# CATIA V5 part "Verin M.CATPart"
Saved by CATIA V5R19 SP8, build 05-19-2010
Part number: Verin M
Bounding box of the stored display mesh (mm): x 178.09 to 425, y 45.135 to 94.865, z -159.495 to 24.818
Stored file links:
  C:\Users\ThinkMotion\Desktop\EU_thinkMotion\iao\IAO_MMS_Groupe3\rdalborgo\rdalborgo\Verin M.CATPart
  C:\Users\ThinkMotion\Desktop\EU_thinkMotion\iao\IAO_MMS_Groupe3\rdalborgo\rdalborgo\rdalborgo.CATProduct
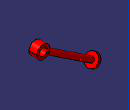
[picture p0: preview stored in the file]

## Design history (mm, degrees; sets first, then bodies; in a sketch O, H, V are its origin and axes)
External parameters (linked from other documents)
  `External.Axe inter diam` = 30 mm
  `External.Axe exter diam` = 50 mm
  `External.Demi epaisseur tete verin` = 15 mm
Set1
  Plane1: linked copy from another document
  Point1 "B verin": linked copy from another document
  Line1: linked copy from another document
  Point2: linked copy from another document
Body1 (main body)
  Sketch1 on Plane1, origin (0, 70, 0), H (-1, 0, 0), V (0, 0, 1)
    circle A1 centre (-400, 0) radius 15
    point P1 (-400, 0)
    circle A2 centre (-400, 0) radius 25
    point P2 (-400, 0)
    reference projected point E1 (-400, 0) from Point1
    radius A1 = 15 {= `External.Axe inter diam` /2}
    radius A2 = 25 {= `External.Axe exter diam` /2}
    coincidence: P2 P1, P2 E1
  Pad1: profile Sketch1, direction (0, 1, 0), length 15 {= `External.Demi epaisseur tete verin`}, mirrored extent
  Sketch2 on Plane1, origin (0, 70, 0), H (-1, 0, 0), V (0, 0, 1)
    line L1 (-387.5192, -8.3205) -> (-191.9556, -138.6963)
    point P2 (-191.9556, -138.6963)
    line L2 (-191.9556, -138.6963) -> (-178.0881, -117.895)
    line L3 (-178.0881, -117.895) -> (-186.4086, -112.348)
    line L4 (-186.4086, -112.348) -> (-194.7291, -124.8288)
    line L5 (-194.7291, -124.8288) -> (-381.9722, 0)
    line L6 (-381.9722, 0) -> (-387.5192, -8.3205)
    reference projected line E1 (-95.8455, -202.7697) -> (-395.8455, -2.7697) from Line1
    reference projected point E2 (-191.9556, -138.6963) from Point2
    reference projected point E3 (-400, 0) from Point1
    distance L5 L1 = 10
    distance L4 L2 = 10
    distance L3 L1 = 25
    distance L6 E3 = 15 {= `External.Axe inter diam` /2}
    perpendicularity: L2 L1
    parallelism: L5 L3, L6 L2
    coincidence: L1 E1, P2 E2
  Shaft1: profile Sketch2, axis Line1, angle 360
